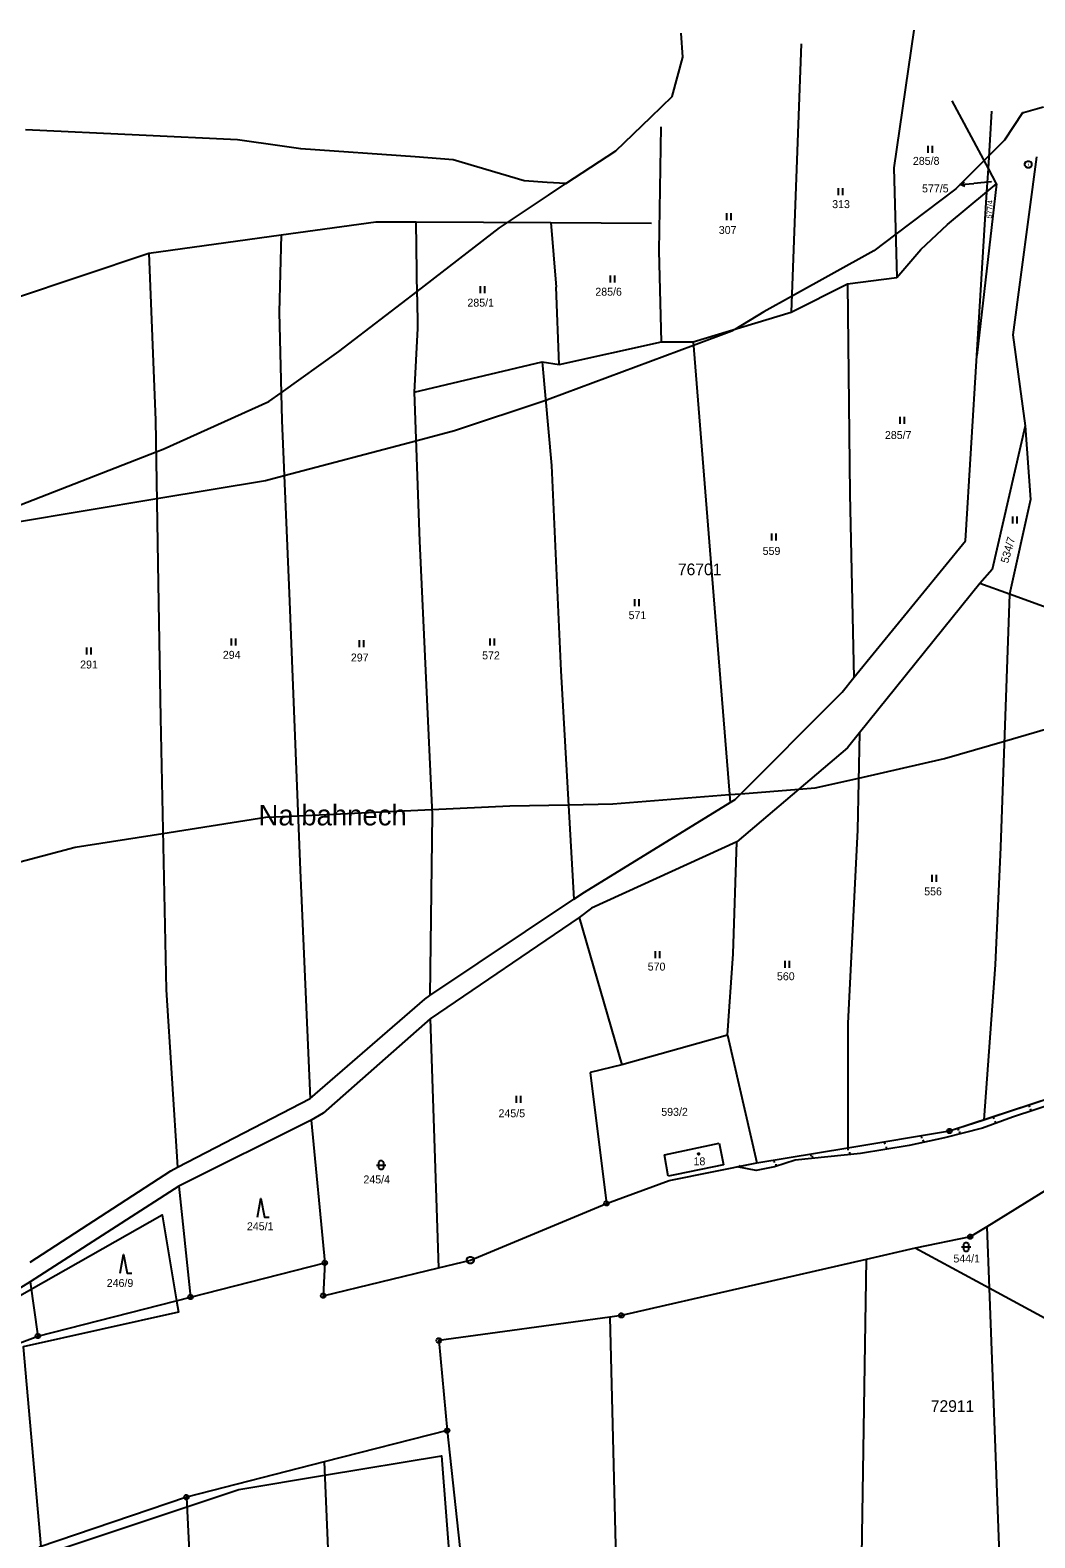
# Model space of a CAD drawing. Extents: x -760978 to -760029, y -1177282 to -1176414.
# Drawn here: x -760827.5 to -760612.3, y -1176736.5 to -1176413.7 of the extents above; entities that cross this region are included whole.
import ezdxf

# ---------------------------------------------------------------- set-up
doc = ezdxf.new("R2010")
doc.units = 0
for name, color, linetype in [('1', 7, 'Continuous'), ('11', 7, 'Continuous'), ('12', 7, 'Continuous'), ('13', 7, 'Continuous'), ('2', 7, 'Continuous'), ('3', 7, 'Continuous'), ('5', 7, 'Continuous'), ('7', 7, 'Continuous'), ('8', 7, 'Continuous')]:
    doc.layers.add(name, color=color, linetype=linetype)

msp = doc.modelspace()

# ---------------------------------------------------------------- linework, layer by layer
at = {"layer": '1'}
for p, q in [((-760638.28, -1176413.74), (-760642.5, -1176443.21)), ((-760662.35, -1176416.66), (-760664.54, -1176474.13)), ((-760622.29, -1176443.34), (-760630.04, -1176428.87)), ((-760622.29, -1176443.34), (-760621.54, -1176431.08)), ((-760692.76, -1176460.99), (-760692.32, -1176434.41)), ((-760611.97, -1176440.89), (-760617.06, -1176478.94)), ((-760642.5, -1176443.21), (-760641.88, -1176466.66)), ((-760622.6, -1176448.36), (-760622.29, -1176443.34)), ((-760620.52, -1176446.65), (-760622.29, -1176443.34)), ((-760620.52, -1176446.65), (-760624.74, -1176483.38)), ((-760622.6, -1176448.36), (-760620.52, -1176446.65)), ((-760631.04, -1176455.32), (-760622.6, -1176448.36)), ((-760624.74, -1176483.38), (-760622.6, -1176448.36)), ((-760773.7, -1176457.57), (-760753.46, -1176454.76)), ((-760753.46, -1176454.76), (-760744.82, -1176454.8)), ((-760744.62, -1176470.83), (-760744.82, -1176454.8)), ((-760744.82, -1176454.8), (-760715.99, -1176454.94)), ((-760715.99, -1176454.94), (-760714.81, -1176468.78)), ((-760715.99, -1176454.94), (-760694.39, -1176455.05)), ((-760636.74, -1176460.71), (-760631.04, -1176455.32)), ((-760802.06, -1176461.5), (-760773.7, -1176457.57)), ((-760773.7, -1176457.57), (-760774.13, -1176474.1)), ((-760641.88, -1176466.66), (-760636.74, -1176460.71)), ((-760831.02, -1176471.17), (-760802.06, -1176461.5)), ((-760802.06, -1176461.5), (-760800.61, -1176497.22)), ((-760692.3, -1176480.47), (-760692.76, -1176460.99)), ((-760652.42, -1176468.04), (-760641.88, -1176466.66)), ((-760714.19, -1176485.34), (-760714.81, -1176468.78)), ((-760664.54, -1176474.13), (-760652.42, -1176468.04)), ((-760652.42, -1176468.04), (-760651.95, -1176513.05)), ((-760744.62, -1176470.83), (-760744.5, -1176477.57)), ((-760774.13, -1176474.1), (-760773.6, -1176497.31)), ((-760685.52, -1176480.47), (-760664.54, -1176474.13)), ((-760744.5, -1176477.57), (-760745.27, -1176491.2)), ((-760617.06, -1176478.94), (-760614.38, -1176498.44)), ((-760714.19, -1176485.34), (-760692.3, -1176480.47)), ((-760692.3, -1176480.47), (-760685.52, -1176480.47)), ((-760685.52, -1176480.47), (-760681.67, -1176528.64)), ((-760745.27, -1176491.2), (-760717.81, -1176484.72)), ((-760717.81, -1176484.72), (-760714.19, -1176485.34)), ((-760717.81, -1176484.72), (-760715.85, -1176506.9)), ((-760627.16, -1176523.04), (-760624.74, -1176483.38)), ((-760745.27, -1176491.2), (-760744.12, -1176523.09)), ((-760800.61, -1176497.22), (-760800.04, -1176532.19)), ((-760773.6, -1176497.31), (-760771.98, -1176534.25)), ((-760614.38, -1176498.44), (-760621.46, -1176529.19)), ((-760614.38, -1176498.44), (-760613.27, -1176514.22)), ((-760715.85, -1176506.9), (-760713.85, -1176550.86)), ((-760651.95, -1176513.05), (-760651.08, -1176552.31)), ((-760613.27, -1176514.22), (-760617.76, -1176534.49)), ((-760744.12, -1176523.09), (-760741.42, -1176581.6)), ((-760651.08, -1176552.31), (-760627.16, -1176523.04)), ((-760681.67, -1176528.64), (-760677.56, -1176579.08)), ((-760621.46, -1176529.19), (-760624.11, -1176532.18)), ((-760800.04, -1176532.19), (-760799.54, -1176560.95)), ((-760771.98, -1176534.25), (-760769.63, -1176593.56)), ((-760624.11, -1176532.18), (-760649.86, -1176564.18)), ((-760617.76, -1176534.49), (-760624.11, -1176532.18)), ((-760617.76, -1176534.49), (-760619.66, -1176588.65)), ((-760593.68, -1176543.24), (-760617.76, -1176534.49)), ((-760713.85, -1176550.86), (-760711.07, -1176599.77)), ((-760653.62, -1176555.41), (-760651.08, -1176552.31)), ((-760676.53, -1176578.45), (-760653.62, -1176555.41)), ((-760799.54, -1176560.95), (-760798.36, -1176619.18)), ((-760649.86, -1176564.18), (-760652.45, -1176567.39)), ((-760649.86, -1176564.18), (-760650.29, -1176584.97)), ((-760652.45, -1176567.39), (-760676.14, -1176587.47)), ((-760708.79, -1176598.24), (-760677.56, -1176579.08)), ((-760677.56, -1176579.08), (-760676.53, -1176578.45)), ((-760741.42, -1176581.6), (-760741.86, -1176620.39)), ((-760650.29, -1176584.97), (-760652.37, -1176626.3)), ((-760676.14, -1176587.47), (-760707.25, -1176601.66)), ((-760676.92, -1176611.42), (-760676.14, -1176587.47)), ((-760619.66, -1176588.65), (-760620.82, -1176613.82)), ((-760769.63, -1176593.56), (-760767.49, -1176642.4)), ((-760711.07, -1176599.77), (-760708.79, -1176598.24)), ((-760741.86, -1176620.39), (-760711.07, -1176599.77)), ((-760707.25, -1176601.66), (-760709.93, -1176603.64)), ((-760709.93, -1176603.64), (-760741.84, -1176625.38)), ((-760709.93, -1176603.64), (-760700.74, -1176635.18)), ((-760678.18, -1176628.88), (-760676.92, -1176611.42)), ((-760620.82, -1176613.82), (-760623.28, -1176646.96)), ((-760798.36, -1176619.18), (-760795.9, -1176657.12)), ((-760767.49, -1176642.4), (-760742.98, -1176621.14)), ((-760742.98, -1176621.14), (-760741.86, -1176620.39)), ((-760741.84, -1176625.38), (-760764.73, -1176645.54)), ((-760741.84, -1176625.38), (-760740.05, -1176678.66)), ((-760652.37, -1176626.3), (-760652.4, -1176652.98)), ((-760678.18, -1176628.88), (-760700.74, -1176635.18)), ((-760678.18, -1176628.88), (-760671.86, -1176656.2)), ((-760700.74, -1176635.18), (-760707.59, -1176636.86)), ((-760707.59, -1176636.86), (-760704.07, -1176664.88)), ((-760795.9, -1176657.12), (-760767.49, -1176642.4)), ((-760623.28, -1176646.96), (-760608.63, -1176642.13)), ((-760767.32, -1176647.02), (-760795.62, -1176661.21)), ((-760764.73, -1176645.54), (-760767.32, -1176647.02)), ((-760767.32, -1176647.02), (-760764.39, -1176677.57)), ((-760630.6, -1176649.37), (-760623.28, -1176646.96)), ((-760652.4, -1176652.98), (-760630.6, -1176649.37)), ((-760691.63, -1176654.5), (-760679.93, -1176652)), ((-760679.93, -1176652), (-760679, -1176656.62)), ((-760671.86, -1176656.2), (-760652.4, -1176652.98)), ((-760797.38, -1176657.89), (-760795.9, -1176657.12)), ((-760690.86, -1176659.02), (-760691.63, -1176654.5)), ((-760690.63, -1176659.96), (-760671.86, -1176656.2)), ((-760679, -1176656.62), (-760689.06, -1176658.65)), ((-760827.49, -1176677.42), (-760797.38, -1176657.89)), ((-760704.07, -1176664.88), (-760690.63, -1176659.96)), ((-760689.06, -1176658.65), (-760690.86, -1176659.02)), ((-760795.62, -1176661.21), (-760827.45, -1176681.66)), ((-760795.62, -1176661.21), (-760793.12, -1176684.92)), ((-760610.03, -1176662.14), (-760622.64, -1176669.86)), ((-760733.2, -1176676.99), (-760704.07, -1176664.88)), ((-760622.64, -1176669.86), (-760626.16, -1176672.02)), ((-760622.64, -1176669.86), (-760622.14, -1176683.02)), ((-760626.16, -1176672.02), (-760637.96, -1176674.45)), ((-760648.45, -1176676.85), (-760700.88, -1176688.86)), ((-760648.45, -1176676.85), (-760649.45, -1176740.28)), ((-760637.96, -1176674.45), (-760648.45, -1176676.85)), ((-760622.14, -1176683.02), (-760637.96, -1176674.45)), ((-760793.12, -1176684.92), (-760764.39, -1176677.57)), ((-760764.39, -1176677.57), (-760764.73, -1176684.64)), ((-760764.73, -1176684.64), (-760740.05, -1176678.66)), ((-760740.05, -1176678.66), (-760733.2, -1176676.99)), ((-760827.45, -1176681.66), (-760858.05, -1176700.53)), ((-760827.45, -1176681.66), (-760825.82, -1176693.28)), ((-760622.14, -1176683.02), (-760619.5, -1176752.88)), ((-760603.68, -1176693.02), (-760622.14, -1176683.02)), ((-760825.82, -1176693.28), (-760793.12, -1176684.92)), ((-760703.31, -1176689.19), (-760739.95, -1176694.23)), ((-760700.88, -1176688.86), (-760703.31, -1176689.19)), ((-760703.31, -1176689.19), (-760700.83, -1176789.13)), ((-760857.74, -1176705.18), (-760825.82, -1176693.28)), ((-760739.95, -1176694.23), (-760738.19, -1176713.51)), ((-760738.19, -1176713.51), (-760764.54, -1176720.19)), ((-760738.19, -1176713.51), (-760731.07, -1176779.15)), ((-760764.54, -1176720.19), (-760794.01, -1176727.76)), ((-760764.54, -1176720.19), (-760754.35, -1176958.32)), ((-760794.01, -1176727.76), (-760825.51, -1176738.43)), ((-760794.01, -1176727.76), (-760783.34, -1176948.16))]:
    msp.add_line(p, q, dxfattribs=at)
at = {"layer": '11'}
for points in [[(-760712.8, -1176446.58), (-760702.07, -1176439.58), (-760694.59, -1176432.37), (-760692.24, -1176430.1), (-760690, -1176427.94), (-760687.74, -1176419.51), (-760688.08, -1176414.42)], [(-760614.95, -1176431.46), (-760618.87, -1176437.32), (-760622.12, -1176440.58), (-760623.19, -1176441.66), (-760629.23, -1176447.72), (-760642.12, -1176457.4), (-760646.84, -1176460.94), (-760664.41, -1176470.72), (-760670.4, -1176474.06), (-760676.61, -1176477.78), (-760677.25, -1176478.16), (-760685.46, -1176481.23), (-760716.1, -1176492.68), (-760717.08, -1176493.01), (-760736.58, -1176499.5), (-760744.89, -1176501.69), (-760773.08, -1176509.13), (-760777.07, -1176510.18), (-760800.34, -1176514.06), (-760831.02, -1176519.18), (-760845.57, -1176521.61)], [(-760610.45, -1176430.21), (-760611.76, -1176430.57), (-760614.8, -1176431.42), (-760614.95, -1176431.46)], [(-760712.8, -1176446.58), (-760716.73, -1176446.32), (-760721.7, -1176445.99), (-760736.9, -1176441.47), (-760745.05, -1176440.89), (-760769.53, -1176439.16), (-760773.49, -1176438.59), (-760783.08, -1176437.21), (-760804.1, -1176436.23), (-760828.44, -1176435.09)], [(-760845.57, -1176521.61), (-760831.02, -1176515.92), (-760800.5, -1176504), (-760799.02, -1176503.42), (-760776.36, -1176493.25), (-760773.74, -1176491.37), (-760761.34, -1176482.52), (-760744.63, -1176469.66), (-760726.95, -1176456.05), (-760725.22, -1176454.9), (-760716.49, -1176449.05), (-760712.8, -1176446.58)], [(-760944.63, -1176642.33), (-760926.29, -1176630.23), (-760922.85, -1176628.66), (-760880.97, -1176609.48), (-760861.64, -1176602.34), (-760841.69, -1176594.96), (-760831.79, -1176592.34), (-760817.83, -1176588.63), (-760799.04, -1176585.67), (-760776.99, -1176582.19), (-760770.09, -1176581.88), (-760741.47, -1176580.56), (-760724.76, -1176579.78), (-760712.22, -1176579.54), (-760702.69, -1176579.35), (-760677.7, -1176577.38), (-760675.27, -1176577.18), (-760662.85, -1176576.2), (-760659.35, -1176575.93), (-760650.06, -1176573.82), (-760631.67, -1176569.67), (-760618.86, -1176565.92), (-760593.94, -1176558.62)], [(-760944.63, -1176642.33), (-760926.19, -1176637.79), (-760926.12, -1176643.12), (-760926.04, -1176648.86), (-760925.91, -1176658.62), (-760922.64, -1176657.35), (-760922.62, -1176658.08), (-760911.82, -1176653.15), (-760892.6, -1176645.69), (-760862, -1176636.06), (-760834.17, -1176627.3), (-760830.05, -1176678.97), (-760829.72, -1176683.06), (-760829.6, -1176684.57), (-760827.23, -1176683.23), (-760799.19, -1176667.34), (-760796.13, -1176685.69), (-760795.71, -1176688.17), (-760828.93, -1176695.59), (-760825.16, -1176738.31)], [(-760825, -1176740.14), (-760793.91, -1176729.81), (-760782.76, -1176726.11), (-760764.42, -1176723.05), (-760739.36, -1176718.88), (-760734.13, -1176787.17)]]:
    msp.add_lwpolyline(points, dxfattribs=at)
at = {"layer": '12'}
for p, q in [((-760691.63, -1176654.5), (-760679.93, -1176652)), ((-760679.93, -1176652), (-760679, -1176656.62)), ((-760690.86, -1176659.02), (-760691.63, -1176654.5)), ((-760679, -1176656.62), (-760689.06, -1176658.65)), ((-760689.06, -1176658.65), (-760690.86, -1176659.02))]:
    msp.add_line(p, q, dxfattribs=at)
at = {"layer": '13'}
for p, q in [((-760613.65, -1176643.79), (-760613.5, -1176644.26)), ((-760613.12, -1176645.12), (-760613.28, -1176644.65)), ((-760621.25, -1176646.29), (-760621.09, -1176646.76)), ((-760620.68, -1176647.75), (-760620.85, -1176647.28)), ((-760636.67, -1176650.38), (-760636.59, -1176650.87)), ((-760628.85, -1176648.79), (-760628.69, -1176649.27)), ((-760628.34, -1176649.99), (-760628.46, -1176649.51)), ((-760660.35, -1176654.3), (-760660.27, -1176654.79)), ((-760652.46, -1176652.99), (-760652.38, -1176653.48)), ((-760651.92, -1176654.39), (-760651.97, -1176653.9)), ((-760644.57, -1176651.68), (-760644.48, -1176652.18)), ((-760644.01, -1176653.23), (-760644.09, -1176652.73)), ((-760636.14, -1176651.77), (-760636.25, -1176651.28)), ((-760675.49, -1176657.17), (-760675.4, -1176656.67)), ((-760668.24, -1176655.6), (-760668.16, -1176656.09)), ((-760667.63, -1176656.97), (-760667.72, -1176656.48)), ((-760659.87, -1176655.21), (-760659.93, -1176654.71))]:
    msp.add_line(p, q, dxfattribs=at)
msp.add_lwpolyline([(-760676.11, -1176657.05), (-760671.86, -1176656.2), (-760652.4, -1176652.98), (-760630.6, -1176649.37), (-760608.63, -1176642.13), (-760592.73, -1176637.28), (-760579.26, -1176633.17), (-760587.45, -1176636.66), (-760591.4, -1176637.58), (-760595.35, -1176638.5), (-760597.84, -1176639.81), (-760607.33, -1176643.21), (-760617.12, -1176646.44), (-760623.53, -1176648.8), (-760631.69, -1176650.82), (-760639.26, -1176652.44), (-760649.65, -1176654.16), (-760663.67, -1176655.6), (-760668.08, -1176657.06), (-760672.02, -1176657.81)], close=True, dxfattribs=at)
at = {"layer": '3'}
for p, q in [((-760635.24, -1176438.5), (-760635.24, -1176440)), ((-760634.24, -1176440), (-760634.24, -1176438.5)), ((-760654.46, -1176447.57), (-760654.46, -1176449.07)), ((-760653.46, -1176449.07), (-760653.46, -1176447.57)), ((-760678.35, -1176452.9), (-760678.35, -1176454.4)), ((-760677.35, -1176454.4), (-760677.35, -1176452.9)), ((-760703.24, -1176466.23), (-760703.24, -1176467.73)), ((-760702.24, -1176467.73), (-760702.24, -1176466.23)), ((-760731.11, -1176468.56), (-760731.11, -1176470.06)), ((-760730.11, -1176470.06), (-760730.11, -1176468.56)), ((-760641.27, -1176496.48), (-760641.27, -1176497.98)), ((-760640.27, -1176497.98), (-760640.27, -1176496.48)), ((-760617.09, -1176517.83), (-760617.09, -1176519.33)), ((-760616.09, -1176519.33), (-760616.09, -1176517.83)), ((-760668.75, -1176521.51), (-760668.75, -1176523.01)), ((-760667.75, -1176523.01), (-760667.75, -1176521.51)), ((-760698.05, -1176535.52), (-760698.05, -1176537.02)), ((-760697.05, -1176537.02), (-760697.05, -1176535.52)), ((-760784.4, -1176543.93), (-760784.4, -1176545.43)), ((-760783.4, -1176545.43), (-760783.4, -1176543.93)), ((-760757.04, -1176544.32), (-760757.04, -1176545.82)), ((-760756.04, -1176545.82), (-760756.04, -1176544.32)), ((-760729.04, -1176543.93), (-760729.04, -1176545.43)), ((-760728.04, -1176545.43), (-760728.04, -1176543.93)), ((-760815.38, -1176545.88), (-760815.38, -1176547.38)), ((-760814.38, -1176547.38), (-760814.38, -1176545.88)), ((-760634.4, -1176594.52), (-760634.4, -1176596.02)), ((-760633.4, -1176596.02), (-760633.4, -1176594.52)), ((-760693.65, -1176610.86), (-760693.65, -1176612.36)), ((-760692.65, -1176612.36), (-760692.65, -1176610.86)), ((-760665.9, -1176612.93), (-760665.9, -1176614.43)), ((-760664.9, -1176614.43), (-760664.9, -1176612.93)), ((-760723.37, -1176641.84), (-760723.37, -1176643.34)), ((-760722.37, -1176643.34), (-760722.37, -1176641.84))]:
    msp.add_line(p, q, dxfattribs=at)
for points in [[(-760753.33, -1176656.66), (-760752.06, -1176656.66), (-760751.33, -1176656.66)], [(-760778.82, -1176667.8), (-760778.07, -1176663.8), (-760777.32, -1176667.8), (-760776.32, -1176667.8)], [(-760808.2, -1176679.79), (-760807.45, -1176675.79), (-760806.7, -1176679.79), (-760805.7, -1176679.79)], [(-760628.06, -1176674.18), (-760626.79, -1176674.18), (-760626.06, -1176674.18)]]:
    msp.add_lwpolyline(points, dxfattribs=at)
for points in [[(-760752.83, -1176656.16), (-760752.73, -1176655.87), (-760752.48, -1176655.69), (-760752.17, -1176655.69), (-760751.92, -1176655.87), (-760751.82, -1176656.16), (-760751.82, -1176657.16), (-760751.92, -1176657.45), (-760752.17, -1176657.63), (-760752.48, -1176657.63), (-760752.73, -1176657.45), (-760752.83, -1176657.16)], [(-760627.56, -1176673.68), (-760627.46, -1176673.39), (-760627.21, -1176673.21), (-760626.9, -1176673.21), (-760626.65, -1176673.39), (-760626.55, -1176673.68), (-760626.55, -1176674.68), (-760626.65, -1176674.97), (-760626.9, -1176675.15), (-760627.21, -1176675.15), (-760627.46, -1176674.97), (-760627.56, -1176674.68)]]:
    msp.add_lwpolyline(points, close=True, dxfattribs=at)
at = {"layer": '5'}
msp.add_lwpolyline([(-760684.35, -1176654.11), (-760684.25, -1176654.13), (-760684.2, -1176654.22), (-760684.18, -1176654.28), (-760684.2, -1176654.37), (-760684.28, -1176654.44), (-760684.35, -1176654.45), (-760684.44, -1176654.42), (-760684.5, -1176654.36), (-760684.52, -1176654.28), (-760684.5, -1176654.19), (-760684.42, -1176654.12)], close=True, dxfattribs=at)
at = {"layer": '7'}
for p in [(-760628.36, -1176446.77), (-760621.61, -1176446.22)]:
    msp.add_line(p, (-760625.37, -1176446.53), dxfattribs=at)
msp.add_lwpolyline([(-760627.32, -1176447.19), (-760628.36, -1176446.77), (-760627.4, -1176446.19)], dxfattribs=at)
at = {"layer": '8'}
for p, q in [((-760613.79, -1176442.49), (-760613.69, -1176442.49)), ((-760630.72, -1176649.37), (-760630.48, -1176649.37)), ((-760704.19, -1176664.88), (-760703.95, -1176664.88)), ((-760626.28, -1176672.02), (-760626.04, -1176672.02)), ((-760764.51, -1176677.57), (-760764.27, -1176677.57)), ((-760733.25, -1176676.99), (-760733.15, -1176676.99)), ((-760793.24, -1176684.92), (-760793, -1176684.92)), ((-760764.85, -1176684.64), (-760764.61, -1176684.64)), ((-760701, -1176688.86), (-760700.76, -1176688.86)), ((-760825.94, -1176693.28), (-760825.7, -1176693.28)), ((-760740.07, -1176694.23), (-760739.83, -1176694.23)), ((-760738.31, -1176713.51), (-760738.07, -1176713.51)), ((-760794.13, -1176727.76), (-760793.89, -1176727.76))]:
    msp.add_line(p, q, dxfattribs=at)
for points in [[(-760613.55, -1176441.77), (-760613.21, -1176441.96), (-760613.02, -1176442.3), (-760613.02, -1176442.69), (-760613.21, -1176443.03), (-760613.55, -1176443.22), (-760613.94, -1176443.22), (-760614.28, -1176443.03), (-760614.47, -1176442.69), (-760614.47, -1176442.3), (-760614.28, -1176441.96), (-760613.94, -1176441.77)], [(-760630.45, -1176648.89), (-760630.2, -1176649.07), (-760630.1, -1176649.36), (-760630.2, -1176649.65), (-760630.45, -1176649.83), (-760630.76, -1176649.83), (-760631.01, -1176649.65), (-760631.11, -1176649.36), (-760631.01, -1176649.07), (-760630.76, -1176648.89)], [(-760703.92, -1176664.4), (-760703.67, -1176664.58), (-760703.57, -1176664.87), (-760703.67, -1176665.16), (-760703.92, -1176665.34), (-760704.23, -1176665.34), (-760704.48, -1176665.16), (-760704.58, -1176664.87), (-760704.48, -1176664.58), (-760704.23, -1176664.4)], [(-760626.01, -1176671.54), (-760625.76, -1176671.72), (-760625.66, -1176672.01), (-760625.76, -1176672.3), (-760626.01, -1176672.48), (-760626.32, -1176672.48), (-760626.57, -1176672.3), (-760626.67, -1176672.01), (-760626.57, -1176671.72), (-760626.32, -1176671.54)], [(-760733.01, -1176676.27), (-760732.67, -1176676.46), (-760732.48, -1176676.8), (-760732.48, -1176677.19), (-760732.67, -1176677.53), (-760733.01, -1176677.72), (-760733.4, -1176677.72), (-760733.74, -1176677.53), (-760733.93, -1176677.19), (-760733.93, -1176676.8), (-760733.74, -1176676.46), (-760733.4, -1176676.27)], [(-760764.24, -1176677.09), (-760763.99, -1176677.27), (-760763.89, -1176677.56), (-760763.99, -1176677.85), (-760764.24, -1176678.03), (-760764.55, -1176678.03), (-760764.8, -1176677.85), (-760764.9, -1176677.56), (-760764.8, -1176677.27), (-760764.55, -1176677.09)], [(-760792.97, -1176684.44), (-760792.72, -1176684.62), (-760792.62, -1176684.91), (-760792.72, -1176685.2), (-760792.97, -1176685.38), (-760793.28, -1176685.38), (-760793.53, -1176685.2), (-760793.63, -1176684.91), (-760793.53, -1176684.62), (-760793.28, -1176684.44)], [(-760764.58, -1176684.16), (-760764.33, -1176684.34), (-760764.23, -1176684.63), (-760764.33, -1176684.92), (-760764.58, -1176685.1), (-760764.89, -1176685.1), (-760765.14, -1176684.92), (-760765.24, -1176684.63), (-760765.14, -1176684.34), (-760764.89, -1176684.16)], [(-760700.73, -1176688.38), (-760700.48, -1176688.56), (-760700.38, -1176688.85), (-760700.48, -1176689.14), (-760700.73, -1176689.32), (-760701.04, -1176689.32), (-760701.29, -1176689.14), (-760701.39, -1176688.85), (-760701.29, -1176688.56), (-760701.04, -1176688.38)], [(-760825.67, -1176692.8), (-760825.42, -1176692.98), (-760825.32, -1176693.27), (-760825.42, -1176693.56), (-760825.67, -1176693.74), (-760825.98, -1176693.74), (-760826.23, -1176693.56), (-760826.33, -1176693.27), (-760826.23, -1176692.98), (-760825.98, -1176692.8)], [(-760739.8, -1176693.75), (-760739.55, -1176693.93), (-760739.45, -1176694.22), (-760739.55, -1176694.51), (-760739.8, -1176694.69), (-760740.11, -1176694.69), (-760740.36, -1176694.51), (-760740.46, -1176694.22), (-760740.36, -1176693.93), (-760740.11, -1176693.75)], [(-760738.04, -1176713.03), (-760737.79, -1176713.21), (-760737.69, -1176713.5), (-760737.79, -1176713.79), (-760738.04, -1176713.97), (-760738.35, -1176713.97), (-760738.6, -1176713.79), (-760738.7, -1176713.5), (-760738.6, -1176713.21), (-760738.35, -1176713.03)], [(-760793.86, -1176727.28), (-760793.61, -1176727.46), (-760793.51, -1176727.75), (-760793.61, -1176728.04), (-760793.86, -1176728.22), (-760794.17, -1176728.22), (-760794.42, -1176728.04), (-760794.52, -1176727.75), (-760794.42, -1176727.46), (-760794.17, -1176727.28)]]:
    msp.add_lwpolyline(points, close=True, dxfattribs=at)

# ---------------------------------------------------------------- texts
at = {"layer": '11'}
for s, p in [('76701', (-760688.76, -1176530.41)), ('72911', (-760634.61, -1176709.5))]:
    msp.add_text(s, height=2.5, dxfattribs=at).set_placement(p)
at = {"layer": '2'}
for s, height, p in [('285/8', 1.7, (-760638.45, -1176442.57)), ('577/5', 0.1, (-760621.81, -1176446.22)), ('313', 1.7, (-760655.73, -1176451.83)), ('307', 1.7, (-760680.01, -1176457.36)), ('285/6', 1.7, (-760706.45, -1176470.58)), ('285/1', 1.7, (-760733.84, -1176472.92)), ('285/7', 1.7, (-760644.44, -1176501.25)), ('559', 1.7, (-760670.62, -1176526.06)), ('571', 1.7, (-760699.33, -1176539.81)), ('294', 1.7, (-760786.21, -1176548.3)), ('297', 1.7, (-760758.79, -1176548.87)), ('572', 1.7, (-760730.69, -1176548.42)), ('291', 1.7, (-760816.76, -1176550.37)), ('556', 1.7, (-760636.03, -1176598.93)), ('570', 1.7, (-760695.23, -1176615.03)), ('560', 1.7, (-760667.56, -1176617.1)), ('245/5', 1.7, (-760727.18, -1176646.43)), ('593/2', 1.7, (-760692.33, -1176646.12)), ('18', 1.7, (-760685.42, -1176656.71)), ('245/4', 1.7, (-760756.11, -1176660.59)), ('245/1', 1.7, (-760781.05, -1176670.61)), ('544/1', 1.7, (-760629.77, -1176677.51)), ('246/9', 1.7, (-760811.07, -1176682.75))]:
    msp.add_text(s, height=height, dxfattribs=at).set_placement(p)
for s, height, rotation, p in [('577/4', 1.14, 86.5739, (-760621.56, -1176454.09)), ('534/7', 1.7, 74.198, (-760618.07, -1176527.97))]:
    msp.add_text(s, height=height, rotation=rotation, dxfattribs=at).set_placement(p)
at = {"layer": '7'}
for s, height, p in [('577/5', 1.7, (-760636.49, -1176448.47)), ('Na bahnech', 4.4, (-760778.56, -1176583.96))]:
    msp.add_text(s, height=height, dxfattribs=at).set_placement(p)

doc.saveas('drawing.dxf')
